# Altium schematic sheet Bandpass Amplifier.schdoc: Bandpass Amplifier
size A4; Organization: Altium Limited; Address1: L3, 12a Rodborough Rd; Address2: Frenchs Forest; Address3: NSW; Address4: Australia 2086; DocumentNumber: 1; SheetNumber: 1; SheetTotal: 1
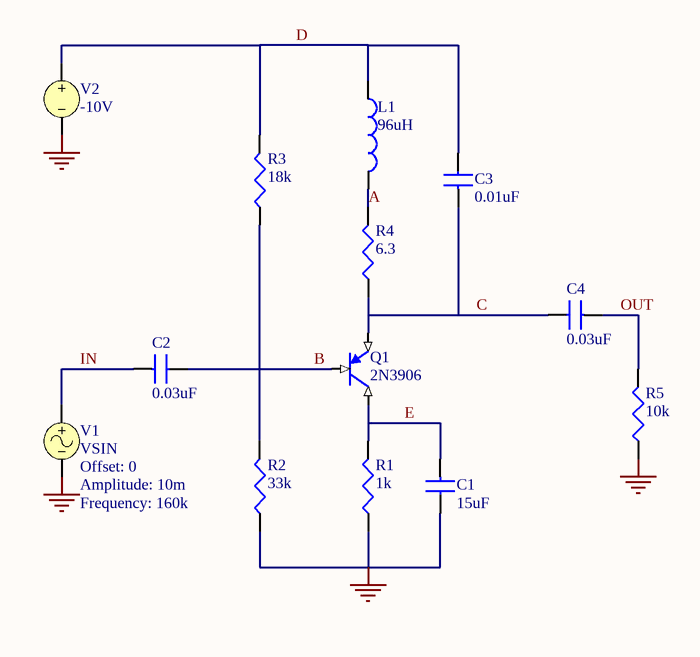
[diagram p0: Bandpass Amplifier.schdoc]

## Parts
C1  15uF
C2  0.03uF
C3  0.01uF
C4  0.03uF
L1  96uH
Q1  2N3906
R1  1k
R2  33k
R3  18k
R4  6.3
R5  10k
V1  VSIN  Offset: 0  Amplitude: 10m  Frequency: 160k
V2  value -10V  (hidden comment: VSRC)

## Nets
GND: C1.2 R1.2(BOT) R2.2(BOT) R5.2(BOT) V1.2 V2.2
A: L1.2 R4.1(TOP)
B: C2.2 Q1.2(B) R2.1(TOP) R3.2(BOT)
C: C3.1 C4.2 Q1.3(E) R4.2(BOT)
D: C3.2 L1.1 R3.1(TOP) V2.1
E: C1.1 Q1.1(C) R1.1(TOP)
IN: C2.1 V1.1
OUT: C4.1 R5.1(TOP)

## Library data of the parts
C1-C4 = CAP: Capacitor
L1 = INDUCTOR
Q1 = 2N3906: PNP BJT
R1-R5 = RES: Resistor
V1 = VSIN: Sinusoidal Voltage Source
V2 = VSRC: Voltage Source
